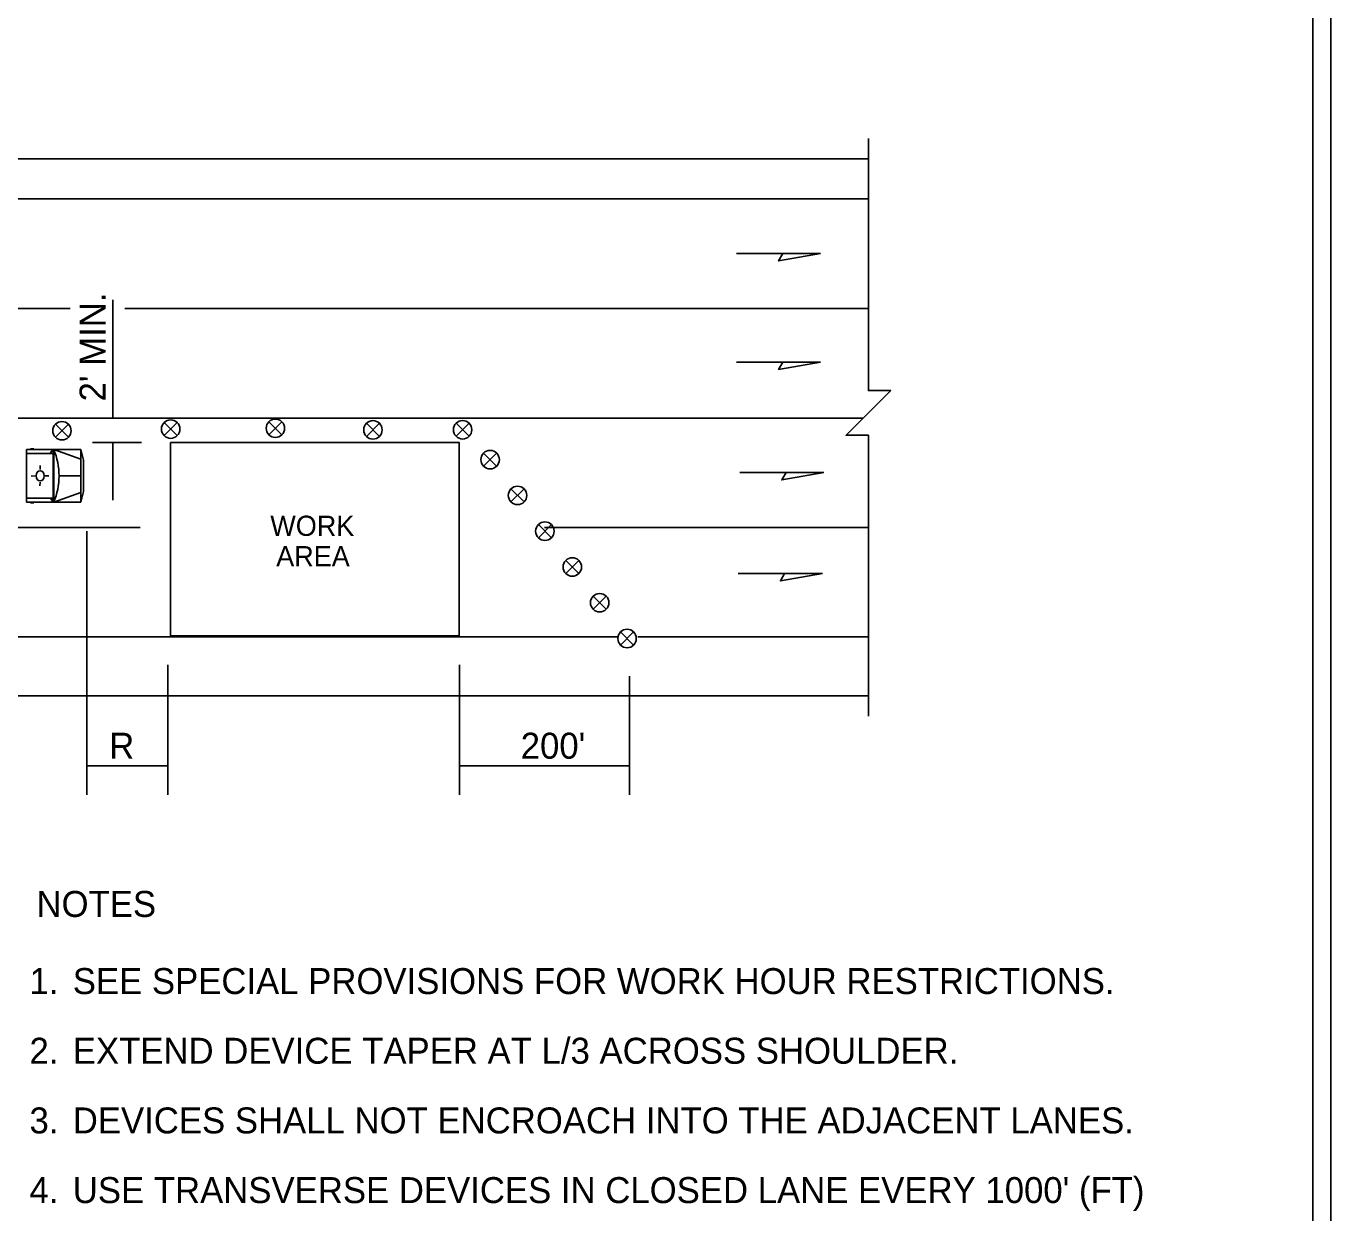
# Model space of a CAD drawing. Extents: x 99988 to 100172, y 99995 to 100047.
# Drawn here: x 100011.29 to 100015.812, y 100002.724 to 100006.837 of the extents above; entities that cross this region are included whole.
import ezdxf

# ---------------------------------------------------------------- set-up
doc = ezdxf.new("R2010")
doc.units = 0
for name, color, linetype in [('Default', 7, 'Continuous'), ('Level 15', 7, 'Continuous'), ('Level 20', 7, 'Continuous'), ('SH_DE_DetailBody1Text', 7, 'Continuous'), ('SH_GI_PlotLimits', 7, 'Continuous'), ('SH_GI_SheetBorder', 7, 'Continuous'), ('SH_GI_TrafficMvmntArrowRt1Lane', 7, 'Continuous'), ('SH_RS_ConstructionNoteFlag', 7, 'Continuous'), ('SH_RS_DimensionLines', 7, 'Continuous'), ('TR_WZ_WorkZoneDetails', 7, 'Continuous')]:
    doc.layers.add(name, color=color, linetype=linetype)

msp = doc.modelspace()

# ---------------------------------------------------------------- linework, layer by layer
at = {"layer": 'Default'}
for p, q in [((100002.5342, 100005.8585), (100011.4419, 100005.8585)), ((100011.6316, 100005.8585), (100014.2061, 100005.8585)), ((100002.5316, 100005.4785), (100014.1914, 100005.4785)), ((100011.8135, 100005.4628), (100011.7682, 100005.4176)), ((100011.7682, 100005.4628), (100011.8135, 100005.4176)), ((100012.1764, 100005.4659), (100012.1312, 100005.4207)), ((100012.1312, 100005.4659), (100012.1764, 100005.4207)), ((100012.5145, 100005.4603), (100012.4693, 100005.4151)), ((100012.4693, 100005.4603), (100012.5145, 100005.4151)), ((100012.7802, 100005.4153), (100012.8254, 100005.4605)), ((100012.8254, 100005.4153), (100012.7802, 100005.4605)), ((100011.4365, 100005.4573), (100011.3912, 100005.412)), ((100011.3912, 100005.4573), (100011.4365, 100005.412)), ((100011.2911, 100005.3698), (100011.2911, 100005.1869)), ((100011.48, 100005.3698), (100011.2911, 100005.3698)), ((100011.3168, 100005.3724), (100011.3055, 100005.3724)), ((100011.3838, 100005.3698), (100011.3718, 100005.3556)), ((100011.3838, 100005.3698), (100011.3838, 100005.1869)), ((100011.3855, 100005.3698), (100011.3855, 100005.1869)), ((100011.48, 100005.3363), (100011.3855, 100005.3698)), ((100011.48, 100005.3698), (100011.48, 100005.1869)), ((100011.48, 100005.3698), (100011.4892, 100005.3329)), ((100011.3838, 100005.3556), (100011.2911, 100005.3556)), ((100011.4892, 100005.3329), (100011.4892, 100005.2238)), ((100012.8755, 100005.3119), (100012.9208, 100005.3571)), ((100012.9208, 100005.3119), (100012.8755, 100005.3571)), ((100011.3076, 100005.2776), (100011.3225, 100005.278)), ((100011.3244, 100005.278), (100011.3244, 100005.278)), ((100011.3385, 100005.3146), (100011.3385, 100005.2998)), ((100011.3686, 100005.2785), (100011.356, 100005.2784)), ((100011.48, 100005.2783), (100011.4041, 100005.2783)), ((100011.3378, 100005.2432), (100011.338, 100005.2569)), ((100012.9705, 100005.1879), (100013.0157, 100005.2332)), ((100013.0157, 100005.1879), (100012.9705, 100005.2332)), ((100011.3838, 100005.2011), (100011.2911, 100005.2011)), ((100011.48, 100005.1869), (100011.2911, 100005.1869)), ((100011.3739, 100005.2011), (100011.3838, 100005.1869)), ((100011.48, 100005.2204), (100011.3855, 100005.1869)), ((100011.48, 100005.1869), (100011.4892, 100005.2238)), ((100011.3168, 100005.1843), (100011.3055, 100005.1843)), ((100002.5342, 100005.0998), (100011.6853, 100005.0998)), ((100013.0654, 100005.064), (100013.1107, 100005.1092)), ((100013.1107, 100005.064), (100013.0654, 100005.1092)), ((100013.0869, 100005.0998), (100014.2061, 100005.0998)), ((100013.1604, 100004.94), (100013.2056, 100004.9853)), ((100013.2056, 100004.94), (100013.1604, 100004.9853)), ((100013.2553, 100004.8161), (100013.3006, 100004.8613)), ((100013.3006, 100004.8161), (100013.2553, 100004.8613)), ((100013.3502, 100004.6921), (100013.3955, 100004.7374)), ((100013.3955, 100004.6921), (100013.3502, 100004.7374))]:
    msp.add_line(p, q, dxfattribs=at)
msp.add_lwpolyline([(100011.7901, 100005.394), (100012.7904, 100005.394), (100012.7904, 100004.724), (100011.7901, 100004.724)], close=True, dxfattribs=at)
for centre in [(100011.4139, 100005.4347), (100011.7909, 100005.4402), (100012.1538, 100005.4433), (100012.4919, 100005.4377), (100012.8028, 100005.4379), (100012.8982, 100005.3345), (100012.9931, 100005.2105), (100013.088, 100005.0866), (100013.183, 100004.9626), (100013.2779, 100004.8387), (100013.3729, 100004.7147)]:
    msp.add_circle(centre, 0.032, dxfattribs=at)
msp.add_ellipse((100011.2505, 100005.2783), major_axis=(0, 0.1919), ratio=0.8, start_param=4.215852, end_param=5.209111, dxfattribs=at)
msp.add_ellipse((100011.3385, 100005.2783), major_axis=(0, -0.0176), ratio=0.8, dxfattribs=at)
at = {"layer": 'Level 15'}
for p, q in [((100011.5182, 100005.4785), (100011.6901, 100005.4785)), ((100011.5197, 100005.394), (100011.6901, 100005.394)), ((100011.5008, 100004.2732), (100011.6411, 100004.2732)), ((100011.7814, 100004.2732), (100011.6411, 100004.2732)), ((100012.7916, 100004.2732), (100013.0866, 100004.2732)), ((100013.3817, 100004.2732), (100013.0866, 100004.2732))]:
    msp.add_line(p, q, dxfattribs=at)
at = {"layer": 'SH_GI_PlotLimits'}
msp.add_lwpolyline([(99999.3125, 99999.9375), (100015.8125, 99999.9375), (100015.8125, 100010.4375), (99999.3125, 100010.4375)], close=True, dxfattribs=at)
at = {"layer": 'SH_GI_SheetBorder'}
msp.add_line((100015.75, 100010.375), (100015.75, 100000), dxfattribs=at)
at = {"layer": 'SH_GI_TrafficMvmntArrowRt1Lane'}
for p, q in [((100013.9127, 100006.0488), (100013.7519, 100006.0488)), ((100013.9127, 100005.6727), (100013.7519, 100005.6727)), ((100013.924, 100005.29), (100013.7633, 100005.29)), ((100013.9191, 100004.94), (100013.7584, 100004.94))]:
    msp.add_line(p, q, dxfattribs=at)
for points in [[(100014.0437, 100006.0488), (100013.8978, 100006.0231), (100013.9127, 100006.0488)], [(100014.0437, 100005.6727), (100013.8978, 100005.647), (100013.9127, 100005.6727)], [(100014.0551, 100005.29), (100013.9092, 100005.2643), (100013.924, 100005.29)], [(100014.0502, 100004.94), (100013.9043, 100004.9143), (100013.9191, 100004.94)]]:
    msp.add_lwpolyline(points, close=True, dxfattribs=at)
at = {"layer": 'SH_RS_DimensionLines'}
for p, q in [((100011.5901, 100005.4785), (100011.5901, 100005.8888)), ((100011.5901, 100005.394), (100011.5901, 100005.194))]:
    msp.add_line(p, q, dxfattribs=at)
at = {"layer": 'TR_WZ_WorkZoneDetails'}
for p, q in [((100002.5342, 100006.3767), (100014.2093, 100006.3767)), ((100009.1315, 100006.2379), (100014.2061, 100006.2379)), ((100011.5008, 100005.0869), (100011.5008, 100004.1732)), ((100009.1206, 100004.7201), (100013.3383, 100004.7201)), ((100013.4096, 100004.7201), (100014.2061, 100004.7201)), ((100011.7814, 100004.624), (100011.7814, 100004.1732)), ((100012.7916, 100004.624), (100012.7916, 100004.1732)), ((100013.3817, 100004.1732), (100013.3817, 100004.584)), ((100009.1133, 100004.5164), (100014.2093, 100004.5164))]:
    msp.add_line(p, q, dxfattribs=at)
msp.add_lwpolyline([(100014.2093, 100006.4475), (100014.2093, 100005.5739), (100014.2868, 100005.5739), (100014.1319, 100005.4191), (100014.2093, 100005.4191), (100014.2093, 100004.4456)], dxfattribs=at)

# ---------------------------------------------------------------- texts
at = {"layer": 'Level 20'}
for s, p in [('R', (100011.5778, 100004.2982)), ("200'", (100013.0042, 100004.2982))]:
    msp.add_text(s, height=0.09, dxfattribs=at).set_placement(p)
at = {"layer": 'SH_DE_DetailBody1Text'}
for s, p in [('WORK', (100012.1361, 100005.0704)), ('AREA', (100012.1567, 100004.9649))]:
    msp.add_text(s, height=0.07, rotation=359.9498, dxfattribs=at).set_placement(p)
for s, p in [('NOTES', (100011.3257, 100003.7499)), ('1.', (100011.3015, 100003.4826)), ('SEE SPECIAL PROVISIONS FOR WORK HOUR RESTRICTIONS.', (100011.4515, 100003.4826)), ('2.', (100011.3015, 100003.2412)), ('EXTEND DEVICE TAPER AT L/3 ACROSS SHOULDER.', (100011.4515, 100003.2412)), ('3.', (100011.3015, 100002.9997)), ('DEVICES SHALL NOT ENCROACH INTO THE ADJACENT LANES.', (100011.4515, 100002.9997)), ('4.', (100011.3015, 100002.7583)), ("USE TRANSVERSE DEVICES IN CLOSED LANE EVERY 1000' (FT)", (100011.4515, 100002.7583))]:
    msp.add_text(s, height=0.09, dxfattribs=at).set_placement(p)
at = {"layer": 'SH_RS_ConstructionNoteFlag'}
msp.add_text("2' MIN.", height=0.09, rotation=90, dxfattribs=at).set_placement((100011.5651, 100005.5362))

doc.saveas('drawing.dxf')
